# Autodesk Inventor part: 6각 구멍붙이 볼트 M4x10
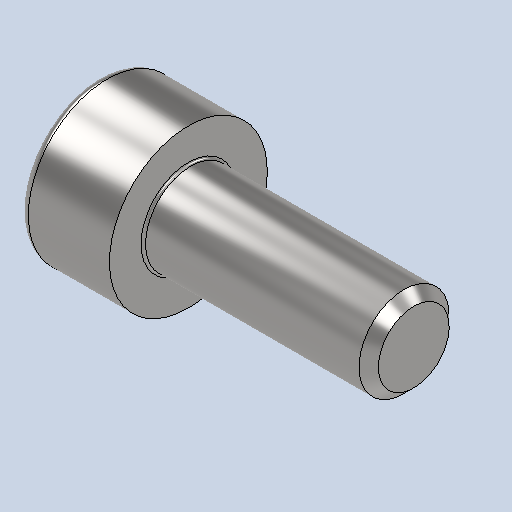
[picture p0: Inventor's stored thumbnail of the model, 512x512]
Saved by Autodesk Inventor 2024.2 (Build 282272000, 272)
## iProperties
Created: 2026-01
Part Number: 6각 구멍붙이 볼트 M4x10
Material: 강철, 연강
Description: 6각머리 태핑 나사
Document SubType Name: Modeling
Designer: home
Density: 7.85 g/cm^3
Appearance: 기본값
Author: jhkim
Sending System: Autodesk Inventor 2026
Preprocessor: ST-DEVELOPER v20.1
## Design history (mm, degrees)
feature "Solid1"
node "솔리드1"
